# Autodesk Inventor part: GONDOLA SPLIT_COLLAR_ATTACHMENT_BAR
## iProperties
Shininess: 64.0
Length Units: 11272
Angle Units: 11279
Time Units: 11290
Mass Units: 11286
Length Display Precision: 3
Angle Display Precision: 2
Compacted: True
Part Number: GONDOLA SPLIT_COLLAR_ATTACHMENT_BAR
Document SubType Name: Modeling
Created: 2004-08
Designer: John Blackburn
Manufacturer: Standard
Standards Organization: Custom
Material: Delrin, Black
Density: 0.0
Volumn: 0.0
Area: 0.0
PropertySet Name: Model Information
Control State: 0
Master: False
Checked Out: False
Author: John Blackburn
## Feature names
1. ExtrusionBlind1
2. ExtrusionThru1
3. AM_HOLE_0301DE_1 [Hole]
4. AM_HOLE_0301DE_2 [Hole]
